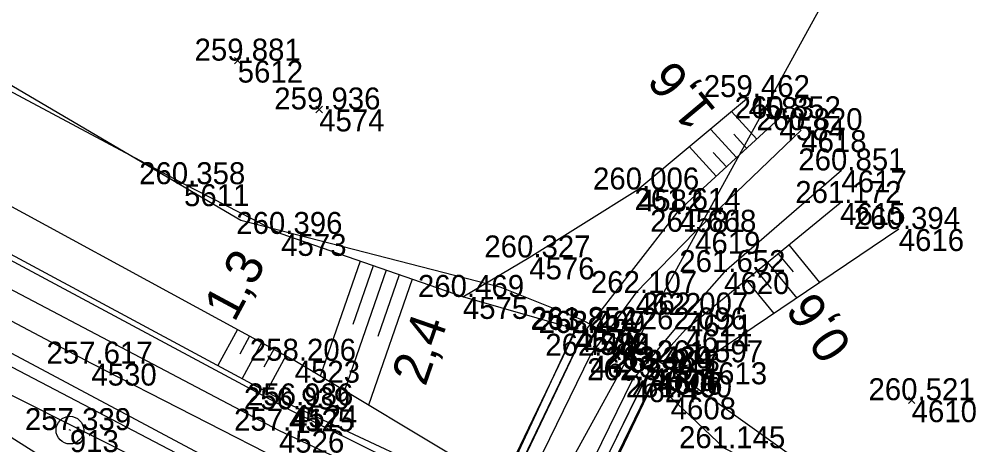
# Model space of a CAD drawing. Extents: x -809970 to -809480, y -1011362 to -1010672.
# Drawn here: x -809650.7 to -809597.8, y -1011219.7 to -1011196.5 of the extents above; entities that cross this region are included whole.
import ezdxf

# ---------------------------------------------------------------- set-up
doc = ezdxf.new("R2010")
doc.units = 0
for name, color, linetype in [('Vrstva 1', 7, 'Continuous'), ('Vrstva 18', 7, 'Continuous'), ('Vrstva 4', 7, 'Continuous'), ('Vrstva 48', 7, 'Continuous'), ('Vrstva 49', 7, 'Continuous'), ('Vrstva 51', 7, 'Continuous'), ('Vrstva 53', 7, 'Continuous'), ('Vrstva 60', 7, 'Continuous'), ('Vrstva 61', 7, 'Continuous'), ('Vrstva 63', 7, 'Continuous')]:
    doc.layers.add(name, color=color, linetype=linetype)

msp = doc.modelspace()

# ---------------------------------------------------------------- linework, layer by layer
at = {"layer": 'Vrstva 1'}
msp.add_lwpolyline([(-809626.114, -1011225.691), (-809635.649, -1011220.957), (-809646.767, -1011215.276), (-809655.525, -1011210.638), (-809661.221, -1011207.519), (-809670.127, -1011202.438), (-809678.476, -1011197.41), (-809686.557, -1011192.275), (-809693.707, -1011187.474), (-809704.479, -1011179.774), (-809716.298, -1011170.61)], dxfattribs=at)
at = {"layer": 'Vrstva 18'}
for p, q in [((-809593.445, -1011171.232), (-809623.882, -1011226.638)), ((-809619.891, -1011213.604), (-809619.869, -1011213.596)), ((-809616.237, -1011215.567), (-809616.208, -1011215.534)), ((-809619.535, -1011223.553), (-809615.787, -1011215.734))]:
    msp.add_line(p, q, dxfattribs=at)
for points in [[(-809620.326, -1011213.386), (-809619.869, -1011213.596), (-809625.685, -1011225.838), (-809631.697, -1011238.186), (-809632.155, -1011237.957), (-809632.143, -1011237.868)], [(-809624.008, -1011221.315), (-809620.326, -1011213.386), (-809620.308, -1011213.436), (-809619.891, -1011213.604), (-809625.755, -1011225.829), (-809631.751, -1011238.049), (-809632.143, -1011237.868)], [(-809620.308, -1011213.436), (-809626.159, -1011225.612), (-809632.143, -1011237.868)], [(-809627.585, -1011240.006), (-809628.019, -1011239.782), (-809622.109, -1011227.503), (-809616.208, -1011215.534), (-809615.787, -1011215.734)], [(-809628.019, -1011239.782), (-809627.986, -1011239.741), (-809622.066, -1011227.511), (-809616.237, -1011215.567)], [(-809616.237, -1011215.567), (-809615.864, -1011215.773), (-809615.787, -1011215.734)], [(-809627.585, -1011240.006), (-809627.565, -1011239.954), (-809621.634, -1011227.677), (-809615.864, -1011215.773)]]:
    msp.add_lwpolyline(points, dxfattribs=at)
at = {"layer": 'Vrstva 4'}
for points in [[(-809514.065, -1011276.667), (-809539.829, -1011264.256), (-809562.291, -1011253.601), (-809585.063, -1011242.594), (-809604.031, -1011233.738), (-809622.746, -1011224.339), (-809635.98, -1011217.776), (-809658.038, -1011205.96), (-809678.208, -1011194.437), (-809694.298, -1011183.842), (-809703.862, -1011176.66), (-809724.9, -1011159.776), (-809744.113, -1011141.604), (-809762.152, -1011122.163), (-809774.569, -1011106.334), (-809789.627, -1011085.975), (-809801.278, -1011067.08), (-809811.536, -1011048.018), (-809817.164, -1011036.691), (-809823.084, -1011022.979)], [(-809514.729, -1011277.553), (-809539.872, -1011265.306), (-809562.717, -1011254.424), (-809585.313, -1011243.688), (-809604.513, -1011234.263), (-809623.3, -1011225.163), (-809636.521, -1011218.939), (-809659.572, -1011206.8), (-809678.109, -1011195.782), (-809694.144, -1011185.083), (-809704.562, -1011177.6), (-809725.723, -1011160.529), (-809745.223, -1011142.426), (-809763.065, -1011123.227), (-809775.618, -1011107.424), (-809790.764, -1011086.703), (-809802.43, -1011068.088), (-809812.884, -1011048.592), (-809818.366, -1011037.45), (-809824.503, -1011023.859)], [(-809516.721, -1011279.856), (-809541.721, -1011267.845), (-809564.358, -1011257.132), (-809585.638, -1011247.052), (-809605.959, -1011237.208), (-809624.348, -1011228.403), (-809638.659, -1011221.376), (-809661.975, -1011208.931), (-809679.174, -1011198.728), (-809694.943, -1011188.715), (-809705.665, -1011180.871), (-809727.898, -1011162.906), (-809747.291, -1011144.847), (-809765.463, -1011125.116), (-809778.441, -1011109.547), (-809793.361, -1011088.57), (-809805.267, -1011069.597), (-809816.065, -1011050.215), (-809821.494, -1011039.157), (-809826.205, -1011028.819)], [(-809517.337, -1011281.17), (-809542.25, -1011268.906), (-809565.048, -1011257.741), (-809585.848, -1011248.029), (-809606.19, -1011237.964), (-809624.44, -1011229.457), (-809639.033, -1011221.782), (-809662.368, -1011209.594), (-809679.748, -1011199.238), (-809695.352, -1011189.158), (-809706.369, -1011181.628), (-809728.711, -1011163.52), (-809748.04, -1011145.819), (-809766.465, -1011126.184), (-809779.347, -1011110.294), (-809779.396, -1011110.263), (-809794.325, -1011089.309), (-809806.506, -1011070.337), (-809817.455, -1011050.768), (-809822.783, -1011039.81), (-809827.652, -1011029.26)]]:
    msp.add_lwpolyline(points, dxfattribs=at)
at = {"layer": 'Vrstva 48'}
for p, q in [((-809610.42, -1011203.01), (-809611.806, -1011201.498)), ((-809611.525, -1011204.024), (-809612.958, -1011202.461)), ((-809610.972, -1011203.517), (-809611.677, -1011202.748)), ((-809612.631, -1011205.037), (-809614.111, -1011203.424)), ((-809612.078, -1011204.53), (-809612.806, -1011203.736)), ((-809609.253, -1011209.27), (-809608.434, -1011210.271)), ((-809608.672, -1011208.795), (-809606.991, -1011210.85)), ((-809632.085, -1011209.688), (-809634.261, -1011215.961)), ((-809609.833, -1011209.745), (-809608.238, -1011211.695)), ((-809630.668, -1011210.179), (-809632.948, -1011216.751)), ((-809631.377, -1011209.934), (-809632.491, -1011213.145)), ((-809610.414, -1011210.22), (-809609.638, -1011211.169)), ((-809629.251, -1011210.671), (-809631.635, -1011217.542)), ((-809629.96, -1011210.425), (-809631.125, -1011213.786)), ((-809610.994, -1011210.695), (-809609.485, -1011212.539)), ((-809638.783, -1011213.421), (-809639.853, -1011215.388)), ((-809638.124, -1011213.78), (-809638.658, -1011214.761)), ((-809637.465, -1011214.138), (-809638.531, -1011216.098)), ((-809636.807, -1011214.496), (-809637.338, -1011215.474)), ((-809636.148, -1011214.854), (-809637.209, -1011216.807))]:
    msp.add_line(p, q, dxfattribs=at)
at = {"layer": 'Vrstva 49'}
for p, q in [((-809638.95, -1011198.547), (-809638.596, -1011198.901)), ((-809638.95, -1011198.901), (-809638.596, -1011198.547)), ((-809634.501, -1011201.215), (-809634.147, -1011201.569)), ((-809634.501, -1011201.569), (-809634.147, -1011201.215)), ((-809602.14, -1011217.098), (-809601.786, -1011217.452)), ((-809602.14, -1011217.452), (-809601.786, -1011217.098))]:
    msp.add_line(p, q, dxfattribs=at)
for points in [[(-809511.612, -1011271.228), (-809536.39, -1011258.331), (-809560.012, -1011246.273), (-809576.21, -1011238.322), (-809612.211, -1011219.896), (-809615.124, -1011217.125), (-809615.787, -1011215.734), (-809619.535, -1011223.553), (-809624.008, -1011221.315), (-809620.326, -1011213.386), (-809626.475, -1011211.634), (-809636.4, -1011208.191), (-809641.706, -1011205.475), (-809669.151, -1011190.804), (-809699.732, -1011169.398), (-809726.539, -1011146.854), (-809748.501, -1011124.908), (-809769.565, -1011100.553), (-809784.985, -1011078.508), (-809794.37, -1011063.913), (-809798.013, -1011059.085), (-809806.772, -1011045.247), (-809814.251, -1011034.457), (-809820.959, -1011021.87)], [(-809517.949, -1011282.175), (-809542.49, -1011269.58), (-809565.628, -1011258.317), (-809585.978, -1011248.403), (-809606.44, -1011238.24), (-809621.618, -1011231.052), (-809624.452, -1011230.402), (-809627.731, -1011228.864), (-809639.591, -1011222.812), (-809662.845, -1011211.141), (-809680.581, -1011200.68), (-809695.918, -1011190.366), (-809707.327, -1011182.303), (-809729.566, -1011164.319), (-809748.842, -1011146.407), (-809766.985, -1011126.934), (-809779.994, -1011110.776), (-809794.753, -1011089.666), (-809807.08, -1011070.596), (-809818.273, -1011051.222), (-809824.251, -1011040.285), (-809829.107, -1011030.235)], [(-809513.006, -1011276.135), (-809534.578, -1011266.087), (-809539.769, -1011263.863), (-809561.922, -1011253.155), (-809584.639, -1011241.913), (-809603.487, -1011232.879), (-809619.732, -1011225.036), (-809620.866, -1011223.988), (-809623.852, -1011222.566), (-809625.317, -1011222.489), (-809635.81, -1011217.558), (-809657.908, -1011205.698), (-809678.345, -1011193.87), (-809696.27, -1011181.606), (-809696.308, -1011181.589), (-809703.94, -1011175.693), (-809724.267, -1011159.214)], [(-809624.008, -1011221.315), (-809625.476, -1011221.249), (-809635.66, -1011215.119), (-809657.282, -1011203.367), (-809678.07, -1011191.699), (-809696.27, -1011181.606), (-809696.308, -1011181.589)], [(-809628.132, -1011229.779), (-809630.068, -1011228.398), (-809632.429, -1011226.947), (-809647.877, -1011221.394), (-809680.581, -1011200.68)], [(-809626.475, -1011211.634), (-809622.85, -1011209.476), (-809616.914, -1011205.765), (-809610.87, -1011200.717)], [(-809620.326, -1011213.386), (-809619.869, -1011213.596), (-809614.652, -1011206.891), (-809609.181, -1011201.874)], [(-809616.208, -1011215.534), (-809614.309, -1011213.408), (-809605.87, -1011206.502)], [(-809602.668, -1011207.925), (-809613.425, -1011215.205), (-809615.787, -1011215.734), (-809616.208, -1011215.534)]]:
    msp.add_lwpolyline(points, dxfattribs=at)
at = {"layer": 'Vrstva 51'}
for points in [[(-809607.993, -1011202.524), (-809613.79, -1011208.073), (-809617.029, -1011211.417), (-809619.521, -1011214.841), (-809625.051, -1011226.184), (-809631.282, -1011238.431), (-809636.132, -1011245.047), (-809643.48, -1011250.941)], [(-809605.796, -1011204.721), (-809612.204, -1011210.276), (-809614.233, -1011212.59), (-809617.231, -1011216.183), (-809622.685, -1011227.335), (-809628.865, -1011239.479), (-809633.897, -1011247.378), (-809641.841, -1011253.414)]]:
    msp.add_lwpolyline(points, dxfattribs=at)
at = {"layer": 'Vrstva 53'}
msp.add_lwpolyline([(-809817.83, -1011024.91), (-809805.06, -1011048.21), (-809777.13, -1011090.84), (-809773.31, -1011095.41), (-809752.3, -1011120.38), (-809722.41, -1011150.52), (-809685.06, -1011180.11), (-809638.61, -1011207.44), (-809624.45, -1011211.08), (-809620, -1011212.86), (-809615.56, -1011215.28), (-809614.76, -1011215.85), (-809598.39, -1011227.55), (-809488.36, -1011283.38)], dxfattribs=at)
at = {"layer": 'Vrstva 60'}
for p, q in [((-809638.773, -1011198.724), (-809638.773, -1011198.724)), ((-809610.87, -1011200.717), (-809610.87, -1011200.717)), ((-809634.324, -1011201.392), (-809634.324, -1011201.392)), ((-809609.181, -1011201.874), (-809609.181, -1011201.874)), ((-809607.993, -1011202.524), (-809607.993, -1011202.524)), ((-809605.796, -1011204.721), (-809605.796, -1011204.721)), ((-809641.706, -1011205.475), (-809641.706, -1011205.475)), ((-809616.914, -1011205.765), (-809616.914, -1011205.765)), ((-809605.87, -1011206.502), (-809605.87, -1011206.502)), ((-809614.652, -1011206.891), (-809614.652, -1011206.891)), ((-809636.4, -1011208.191), (-809636.4, -1011208.191)), ((-809613.79, -1011208.073), (-809613.79, -1011208.073)), ((-809602.668, -1011207.925), (-809602.668, -1011207.925)), ((-809622.85, -1011209.476), (-809622.85, -1011209.476)), ((-809612.204, -1011210.276), (-809612.204, -1011210.276)), ((-809617.029, -1011211.417), (-809617.029, -1011211.417)), ((-809626.475, -1011211.634), (-809626.475, -1011211.634)), ((-809614.233, -1011212.59), (-809614.233, -1011212.59)), ((-809620.326, -1011213.386), (-809620.326, -1011213.386)), ((-809620.308, -1011213.436), (-809620.308, -1011213.436)), ((-809614.309, -1011213.408), (-809614.309, -1011213.408)), ((-809619.891, -1011213.604), (-809619.891, -1011213.604)), ((-809619.869, -1011213.596), (-809619.869, -1011213.596)), ((-809635.66, -1011215.119), (-809635.66, -1011215.119)), ((-809619.521, -1011214.841), (-809619.521, -1011214.841)), ((-809646.767, -1011215.276), (-809646.767, -1011215.276)), ((-809616.237, -1011215.567), (-809616.237, -1011215.567)), ((-809616.208, -1011215.534), (-809616.208, -1011215.534)), ((-809613.425, -1011215.205), (-809613.425, -1011215.205)), ((-809617.231, -1011216.183), (-809617.231, -1011216.183)), ((-809615.864, -1011215.773), (-809615.864, -1011215.773)), ((-809615.787, -1011215.734), (-809615.787, -1011215.734)), ((-809615.124, -1011217.125), (-809615.124, -1011217.125)), ((-809635.81, -1011217.558), (-809635.81, -1011217.558)), ((-809601.963, -1011217.275), (-809601.963, -1011217.275)), ((-809635.98, -1011217.776), (-809635.98, -1011217.776)), ((-809647.941, -1011218.91), (-809647.941, -1011218.91)), ((-809636.521, -1011218.939), (-809636.521, -1011218.939))]:
    msp.add_line(p, q, dxfattribs=at)
at = {"layer": 'Vrstva 63'}
msp.add_line((-809647.896, -1011218.933), (-809647.986, -1011218.887), dxfattribs=at)
msp.add_circle((-809647.941, -1011218.91), 0.756, dxfattribs=at)

# ---------------------------------------------------------------- texts
at = {"layer": 'Vrstva 48'}
for s, rotation, p in [('1,6', 129.8689, (-809612.58, -1011201.44)), ('1,3', 61.7775, (-809638.955, -1011213.067)), ('0,6', 124.0889, (-809605.166, -1011214.299)), ('2,4', 70.8682, (-809628.524, -1011216.57))]:
    msp.add_text(s, height=2, rotation=rotation, dxfattribs=at).set_placement(p)
at = {"layer": 'Vrstva 60'}
for s, p in [('5612', (-809638.773, -1011199.924)), ('4583', (-809610.87, -1011201.917)), ('4574', (-809634.324, -1011202.592)), ('4584', (-809609.181, -1011203.074)), ('4618', (-809607.993, -1011203.724)), ('4617', (-809605.796, -1011205.921)), ('5611', (-809641.706, -1011206.675)), ('4582', (-809616.914, -1011206.965)), ('4615', (-809605.87, -1011207.702)), ('4581', (-809614.652, -1011208.091)), ('4573', (-809636.4, -1011209.391)), ('4619', (-809613.79, -1011209.273)), ('4616', (-809602.668, -1011209.125)), ('4576', (-809622.85, -1011210.676)), ('4620', (-809612.204, -1011211.476)), ('4622', (-809617.029, -1011212.617)), ('4575', (-809626.475, -1011212.834)), ('4621', (-809614.233, -1011213.79)), ('4577', (-809620.326, -1011214.586)), ('4579', (-809620.308, -1011214.636)), ('4614', (-809614.309, -1011214.608)), ('4580', (-809619.891, -1011214.804)), ('4578', (-809619.869, -1011214.796)), ('4523', (-809635.66, -1011216.319)), ('4623', (-809619.521, -1011216.041)), ('4530', (-809646.767, -1011216.476)), ('4605', (-809616.237, -1011216.767)), ('4604', (-809616.208, -1011216.734)), ('4613', (-809613.425, -1011216.405)), ('4624', (-809617.231, -1011217.383)), ('4606', (-809615.864, -1011216.973)), ('4607', (-809615.787, -1011216.934)), ('4608', (-809615.124, -1011218.325)), ('4525', (-809635.98, -1011218.976)), ('4524', (-809635.81, -1011218.758)), ('4610', (-809601.963, -1011218.475)), ('913', (-809647.941, -1011220.11)), ('4526', (-809636.521, -1011220.139))]:
    msp.add_text(s, height=1.2, dxfattribs=at).set_placement(p)
at = {"layer": 'Vrstva 61'}
for s, p in [('259.881', (-809641.13, -1011198.724)), ('259.462', (-809613.318, -1011200.717)), ('259.936', (-809636.776, -1011201.392)), ('260.852', (-809611.629, -1011201.874)), ('260.820', (-809610.444, -1011202.524)), ('260.851', (-809608.153, -1011204.721)), ('260.358', (-809644.16, -1011205.475)), ('260.006', (-809619.366, -1011205.765)), ('261.172', (-809608.318, -1011206.502)), ('261.614', (-809617.103, -1011206.891)), ('260.396', (-809638.852, -1011208.191)), ('261.668', (-809616.244, -1011208.073)), ('260.394', (-809605.119, -1011207.925)), ('260.327', (-809625.302, -1011209.476)), ('261.652', (-809614.652, -1011210.276)), ('262.107', (-809619.481, -1011211.417)), ('260.469', (-809628.929, -1011211.634)), ('262.007', (-809616.685, -1011212.59)), ('261.852', (-809622.774, -1011213.386)), ('263.254', (-809622.759, -1011213.436)), ('263.267', (-809622.343, -1011213.604)), ('262.409', (-809622.323, -1011213.596)), ('262.096', (-809616.761, -1011213.408)), ('257.617', (-809649.219, -1011215.276)), ('258.206', (-809638.112, -1011215.119)), ('262.484', (-809621.972, -1011214.841)), ('261.597', (-809615.877, -1011215.205)), ('263.324', (-809618.688, -1011215.567)), ('262.439', (-809618.662, -1011215.534)), ('263.327', (-809618.316, -1011215.773)), ('262.013', (-809618.239, -1011215.734)), ('262.389', (-809619.685, -1011216.183)), ('261.460', (-809617.575, -1011217.125)), ('260.521', (-809604.32, -1011217.275)), ('256.939', (-809638.434, -1011217.776)), ('256.986', (-809638.262, -1011217.558)), ('257.339', (-809650.395, -1011218.91)), ('257.417', (-809638.973, -1011218.939)), ('261.145', (-809614.667, -1011219.896))]:
    msp.add_text(s, height=1.2, dxfattribs=at).set_placement(p)

doc.saveas('drawing.dxf')
